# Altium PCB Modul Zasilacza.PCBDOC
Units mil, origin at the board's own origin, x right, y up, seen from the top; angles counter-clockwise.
Board outline 6000 x 4000 mil, 2 copper layers (Top Layer, Bottom Layer); 31 components, 26 nets, 83 pads, 0 vias.
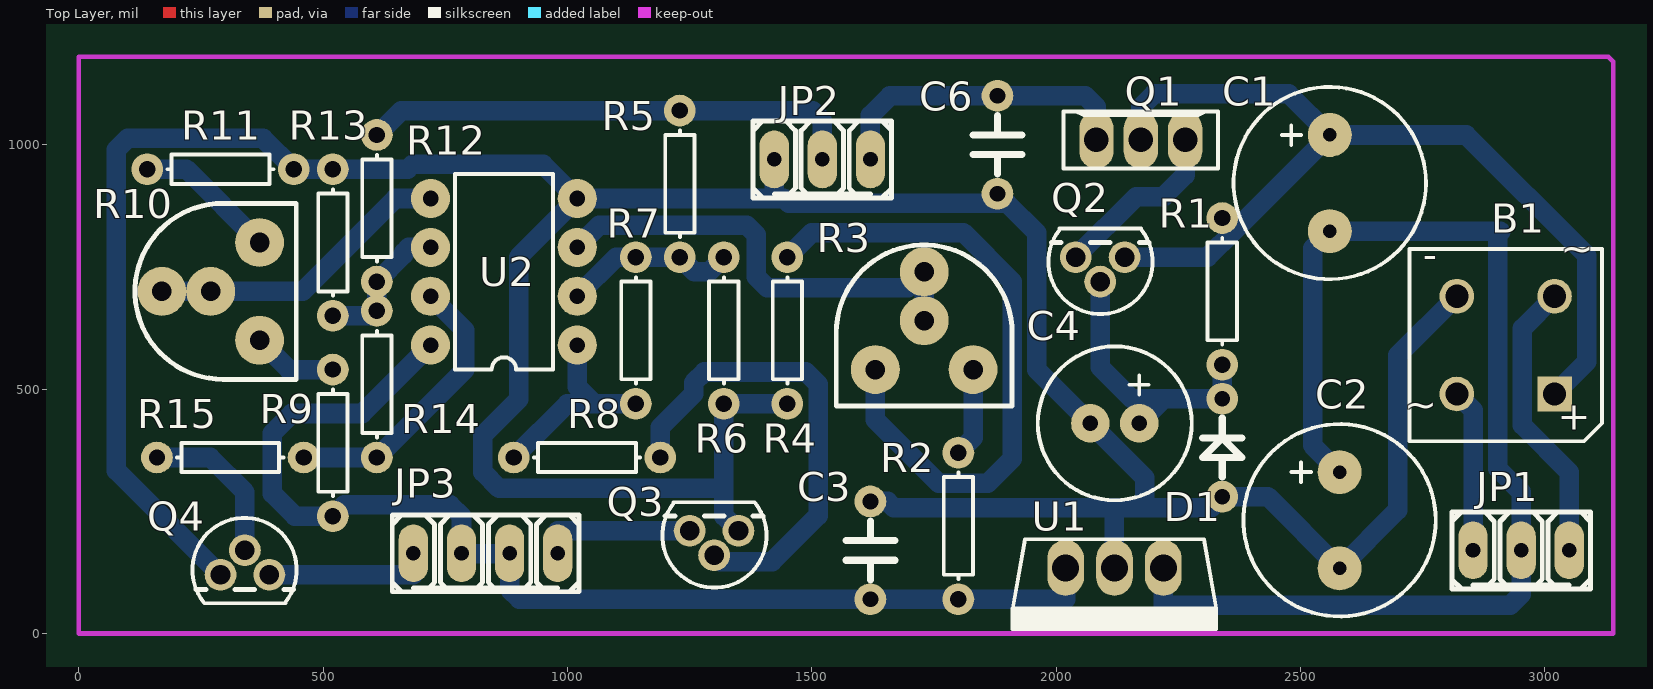
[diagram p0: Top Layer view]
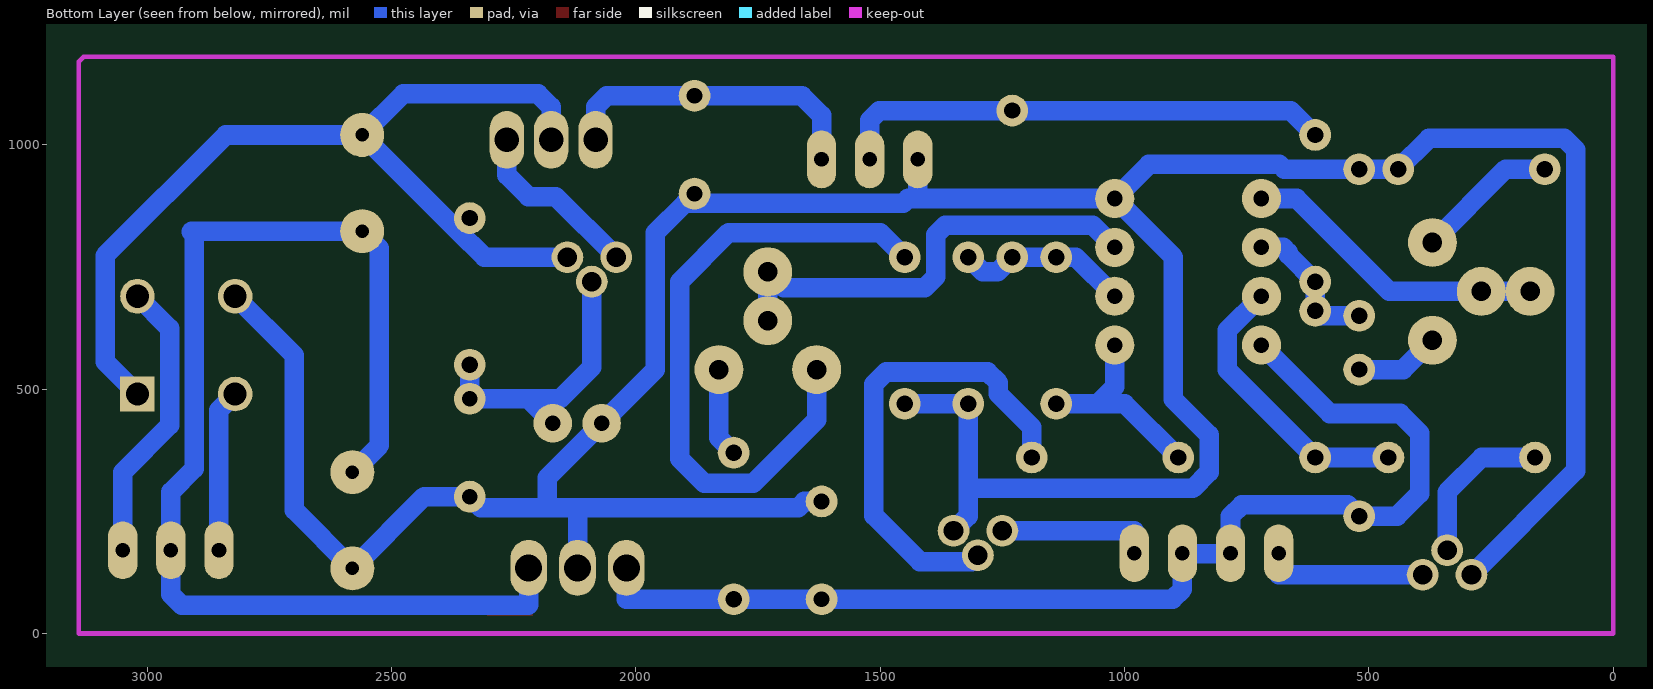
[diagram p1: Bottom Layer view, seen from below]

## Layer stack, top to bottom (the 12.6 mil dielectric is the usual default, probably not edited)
Top Layer: signal copper 1.4
Dielectric: dielectric 12.6, FR-4, Dk 4.8
Bottom Layer: signal copper 1.4

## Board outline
-2180,-1430 3820,-1430 3820,2570 -2180,2570

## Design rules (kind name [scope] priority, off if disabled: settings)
Clearance [All] p1: gap=10
ComponentClearance [All] p1: gap=10 collisioncheckmode=0
PolygonConnect [All] p1: connectstyle=Relief reliefconductorwidth=10 reliefentries=4 polygonreliefangle="90 Angle"
RoomDefinition "Modul Zasialcza" [InComponentClass('Modul Zasialcza')] p1: confinementstyle=ConfineIn formatcopy=TRUE outline -3180,-2430 -1180,-2430 -1180,-1430 -3180,-1430
RoutingLayers [All] p1: top layer="Not Used" bottom layer=Vertical
RoutingVias [All] p1: holewidth=78 width=100 viastyle="Through Hole" minholewidth=78 minwidth=100 maxholewidth=78 maxwidth=100
SolderMaskExpansion [All] p1: expansion=4
TestPointUsage [All] p1: valid=0 allowmultiple=FALSE
Testpoint [All] p1: side=15 testpointundercomponent=TRUE minsize=40 maxsize=100 preferedsize=60 minholesize=0 maxholesize=40 preferedholesize=32 testpointgrid=1 style=1023 order=-539222988
Width Standard [All] p1: maxlimit=50 minlimit=10 preferedwidth=10 toplayer_minwidth=30 toplayer_prefwidth=40 bottomlayer_minwidth=30 bottomlayer_prefwidth=40 minimp=50.000000 maximp=50.000000 favimp=50.000000
Width [All] p2: maxlimit=10 minlimit=10 preferedwidth=10
16 further rules are at their usual default settings.

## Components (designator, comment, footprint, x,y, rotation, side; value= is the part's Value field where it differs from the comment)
B1 "Bridge1" E-BIP-P4/D10 2920,590 r180 top (schematic designator D?)
C1 "1000uF/25V" "C el./5mm" 2560,1020 r270 top
C2 "1000uF/25V" "C el./5mm" 2580,330 r270 top
C3 "100nF" C2 1620,270 r270 top
C4 "100uF/35V" "C el./2.5mm" 2170,430 r180 top
C6 "100nF" C2 1880,1100 r270 top
D1 "33V" D2 2340,280 r90 top
JP1 "2x12VAC" JP3 3050,170 r180 top
JP2 "33V&Pomiar" JP3 1620,970 r180 top
JP3 "2xPrzekaznik" JP4 980,160 r180 top
Q1 "BD139" TO126V 2170,1010 r0 top
Q2 "BC546" TO92 2140,770 r270 top
Q3 "BC556" TO92 1350,210 r270 top
Q4 "BC556" TO92 290,120 r90 top
R1 "1K" AXIAL-0.3 2340,700 r270 top
R2 "22K" AXIAL-0.3 1800,220 r90 top
R3 "4,7K" PR5 1630,540 r0 top
R4 "560" AXIAL-0.3 1450,620 r270 top
R5 "680K" AXIAL-0.3 1230,920 r270 top
R6 "56K" AXIAL-0.3 1320,620 r270 top
R7 "4,7M" AXIAL-0.3 1140,620 r270 top
R8 "4,7K" AXIAL-0.3 1040,360 r0 top
R9 "22K" AXIAL-0.3 520,390 r90 top
R10 "4,7K" PR5 370,600 r90 top
R11 "560" AXIAL-0.3 290,950 r0 top
R12 "680K" AXIAL-0.3 610,870 r270 top
R13 "56K" AXIAL-0.3 520,800 r90 top
R14 "4,7M" AXIAL-0.3 610,510 r270 top
R15 "4,7K" AXIAL-0.3 310,360 r180 top
U1 "7812" TO220v 2119.69,130 r180 top
U2 "LM358" U8 1020,590 r90 top

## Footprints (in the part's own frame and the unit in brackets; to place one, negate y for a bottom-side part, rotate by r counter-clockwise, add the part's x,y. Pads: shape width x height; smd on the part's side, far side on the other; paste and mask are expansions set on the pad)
AXIAL-0.3 [mil]
  round 65 hole 33.46: 1(-150,0) 2(150,0)
  silkscreen extent -109,-30 109,30
C2 [mil]
  round 65 hole 32: 1(0,0) 2(200,0)
  silkscreen extent 40,-50 160,50
"C el./2.5mm" [mm]
  round 2 hole 0.8: 1(0,0) 2(2.54,0)
  silkscreen extent -2.73,-4 5.27,4
"C el./5mm" [mil]
  round 90 hole 27.56: 1(0,0) 2(196.85,0)
  silkscreen extent -98,-197 295,197
D2 [mil]
  round 65 hole 32: 1(0,0) 2(200,0)
  silkscreen extent 40,-40 160,40
E-BIP-P4/D10 [mm]
  rect 1.8x1.8 hole 1.2: 1(-2.54,2.54)
  round 1.8 hole 1.2: 2(-2.54,-2.54) 3(2.54,-2.54) 4(2.54,2.54)
  silkscreen extent -5,-5 5,5
JP3 [mil]
  oval 60x118.11 hole 30: 1(0,0) 2(98.43,0) 3(196.85,0)
  silkscreen extent -43,-79 240,79
JP4 [mil]
  oval 60x118.11 hole 30: 1(0,-3.94) 2(98.43,-3.94) 3(196.85,-3.94) 4(295.28,-3.94)
  silkscreen extent -43,-83 339,75
PR5 [mil]
  round 100 hole 40: 1(0,0) 2(100,100) 2(100,200) 3(200,0)
  silkscreen extent -80,-75 280,255
TO92 [mil]
  round 65 hole 40: 1(0,-100) 2(50,-50) 3(0,0)
  silkscreen extent -58,-156 116,57
TO126V [mil]
  oval 70x118.11 hole 50: 1(3.27,0) 2(94.11,0) 3(-87.56,0)
  silkscreen extent -155,-58 162,58
TO220v [mil]
  oval 75x114.37 hole 55: 1(-99.69,-4.25) 2(0.31,-4.25) 3(100.31,-4.25)
  Top Layer region: -185.04,86.61 -90.55,86.61 -90.55,94.49 -185.04,94.49
  silkscreen extent -208,-63 209,122
U8 [mil]
  round 80 hole 32: 1(0,0) 2(100,0) 3(200,0) 4(300,0) 5(300,300) 6(200,300) 7(100,300) 8(0,300)
  silkscreen extent -50,50 350,250

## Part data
B1: "Full Wave Diode Bridge"
C1 C2 C4: library part CAP2, "kONDENSATOR ELEKTROLITYCZNY"
C3 C6: library part CAP, "Condenstor"
D1: library part BZX55C4V7, "Dioda zenera"
JP1 JP2: library part JP3, "ZLACZE 3 STYKOWE"
JP3: library part JP4, "ZLACZE 4 STYKOWE"
Q1: "Tranzystor"
Q2: library part NPN, "Tranzystor NPN"
Q3 Q4: library part PNP, "Tranzystor PNP"
R1 R2 R4 R5 R6 R7 R8 R9 R11 R12 R13 R14 R15: library part RES, "Rezystor"
R3 R10: library part RPOT, "Potencjometr"
U1: library part 78XX, "@ 3-Terminal Positive Voltage Regulator"
U2: "Low-Noise JFET-Input Operational Amplifiers"

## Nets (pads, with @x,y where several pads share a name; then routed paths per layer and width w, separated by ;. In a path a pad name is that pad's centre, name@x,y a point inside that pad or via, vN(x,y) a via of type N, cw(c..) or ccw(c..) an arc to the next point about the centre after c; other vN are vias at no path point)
NetC1_1: B1.1 C1.1 Q1.1 Q2.3 R1.1 | length 1997.4
  Bottom Layer w40: Q2.3 2310,770 2365,825 ; Q1.1 2173.27,1077.27 2200,1104 2476,1104 C1.1 ; R1.1 2365,825 ; B1.1 3086,556 3086,773 2839,1020 C1.1 ; 2365,825 C1.1
NetC1_2: C1.2 C2.1 JP1.2 U1.1 | length 2462.1
  Bottom Layer w40: U1.1 2219.37,59 2220.37,58 2929.57,58 2951.57,80 JP1.2 2951.57,289.43 2904,337 2904,816 2910,822 2908.85,823.15 C1.2 2525,788.15 2525,385 C2.1
NetC2_2: B1.3 C2.2 C3.1 C4.2 C6.2 D1.1 JP2.3 Q3.3 Q4.3 R4.2 R6.2 R11.2 R13.2 U1.2 U2.4 | length 7057.4
  Bottom Layer w40: Q4.3 77,333 77,990 100,1013 377,1013 R11.2 R13.2 673,950 683,960 950,960 U2.4 ; Q3.3 1320,240 1320,297 ; JP2.3 1423.15,890 ; R4.2 R6.2 1320,297 ; C3.1 1655,270 1668,257 2119.37,257 ; C6.2 C6.2@1880,880 ; U1.2 2119.37,257 ; B1.3 2699,569 2699,252.15 C2.2 2433.15,280 D1.1 2317,257 2181.19,257 ; U2.4 1423.15,890 ; U2.4 900,770 900,479 827,406 827,330 860,297 1320,297 ; 1423.15,890 1443.15,890 1453.15,880 C6.2@1880,880 ; C6.2@1880,880 1900,880 1960,820 1960,540 C4.2 2181.19,318.81 2181.19,257 ; 2119.37,257 2181.19,257
NetC3_2: C3.2 JP3.2 JP3.3 R2.1 R9.1 U1.3 U2.8 | length 2407.4
  Bottom Layer w40: U2.8 580,450 436,450 396,410 396,286 442,240 R9.1 543,263 760,263 783.15,239.85 JP3.3 783.15,163 JP3.2@881.57,163 ; JP3.2 JP3.2@881.57,163 ; U1.3 2019.37,70 R2.1 C3.2 901.57,70 881.57,90 JP3.2@881.57,163
NetC4_1: C4.1 D1.2 Q2.2 R1.2 | length 592.6
  Bottom Layer w40: Q2.2 2090,545 2155,480 2170,480 2220,480 ; C4.1 2220,480 ; R1.2 D1.2 2220,480
NetC6_2: C6.1 JP2.1 Q1.3 | length 645.9
  Bottom Layer w40: JP2.1 1620,1060 1660,1100 C6.1 2060,1100 2082.44,1077.56 Q1.3
NetD?_2: B1.2 JP1.1 | length 587.1
  Bottom Layer w40: B1.2 2954,624 2954,426 3050,330 JP1.1
NetD?_4: B1.4 JP1.3 | length 333.7
  Bottom Layer w40: B1.4 2853.15,456.85 JP1.3
NetJP1_1: 
NetJP1_3: 
NetJP2_2: JP2.2 R5.1 R12.1 | length 1020.6
  Bottom Layer w40: R12.1 660,1070 R5.1 1501.57,1070 1521.57,1050 JP2.2
NetJP3_1: JP3.1 Q3.1 | length 316.1
  Bottom Layer w40: JP3.1 980,210 Q3.1
NetJP3_4: JP3.4 Q4.1 | length 338.7
  Bottom Layer w40: Q4.1 684.72,120 JP3.4
NetQ1_2: Q1.2 Q2.1 | length 365.6
  Bottom Layer w40: Q2.1 2164,894 2220,894 2264.11,938.11 Q1.2
NetQ3_2: Q3.2 R8.2 | length 982
  Bottom Layer w40: R8.2 1190,422 1258,490 1258,513 1280,535 1488,535 1513,510 1513,241 1419,147 1313,147 Q3.2
NetQ4_2: Q4.2 R15.2 | length 328.4
  Bottom Layer w40: R15.2 269,360 340,289 Q4.2
NetR2_2: R2.2 R3.3 | length 182.4
  Bottom Layer w40: R2.2 1830,400 R3.3
NetR3_2: R3.1 R4.1 | length 1342.7
  Bottom Layer w40: R4.1 1500,820 1810,820 1910,720 1910,357 1860,307 1760,307 1630,437 R3.1
NetR3_3: R3.2 U2.3 | length 945.7
  Bottom Layer w40: U2.3 1065,835 1367,835 1386,816 1386,730 1409,707 1697,707 1730,740 R3.2@1730,640
NetR5_2: R5.2 R6.1 R7.1 U2.2 | length 358
  Bottom Layer w40: U2.2 1100,770 R7.1 R5.2 1260,740 1290,740 R6.1
NetR7_2: R7.2 R8.1 U2.1 | length 430.1
  Bottom Layer w40: R8.1 1000,470 1055,470 ; U2.1 1020,505 1055,470 ; R7.2 1055,470
NetR9_2: R9.2 R10.1 | length 174.9
  Bottom Layer w40: R10.1 430,540 R9.2
NetR10_2: R10.3 R11.1 | length 292.1
  Bottom Layer w40: R11.1 220,950 R10.3
NetR10_3: R10.2 U2.5 | length 628.7
  Bottom Layer w40: R10.2@170,700 270,700 458,700 648,890 U2.5
NetR12_2: R12.2 R13.1 R14.1 U2.6 | length 296.1
  Bottom Layer w40: R13.1 600,650 R14.1 R12.2 665,775 665,780 675,790 U2.6
NetR14_2: R14.2 R15.1 U2.7 | length 583.6
  Bottom Layer w40: R15.1 R14.2 790,540 790,620 U2.7

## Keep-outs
Keep-Out Layer:
  lines w10: 0,0 0,1180 40,1180 3130,1180 3140,1170 3140,0 0,0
